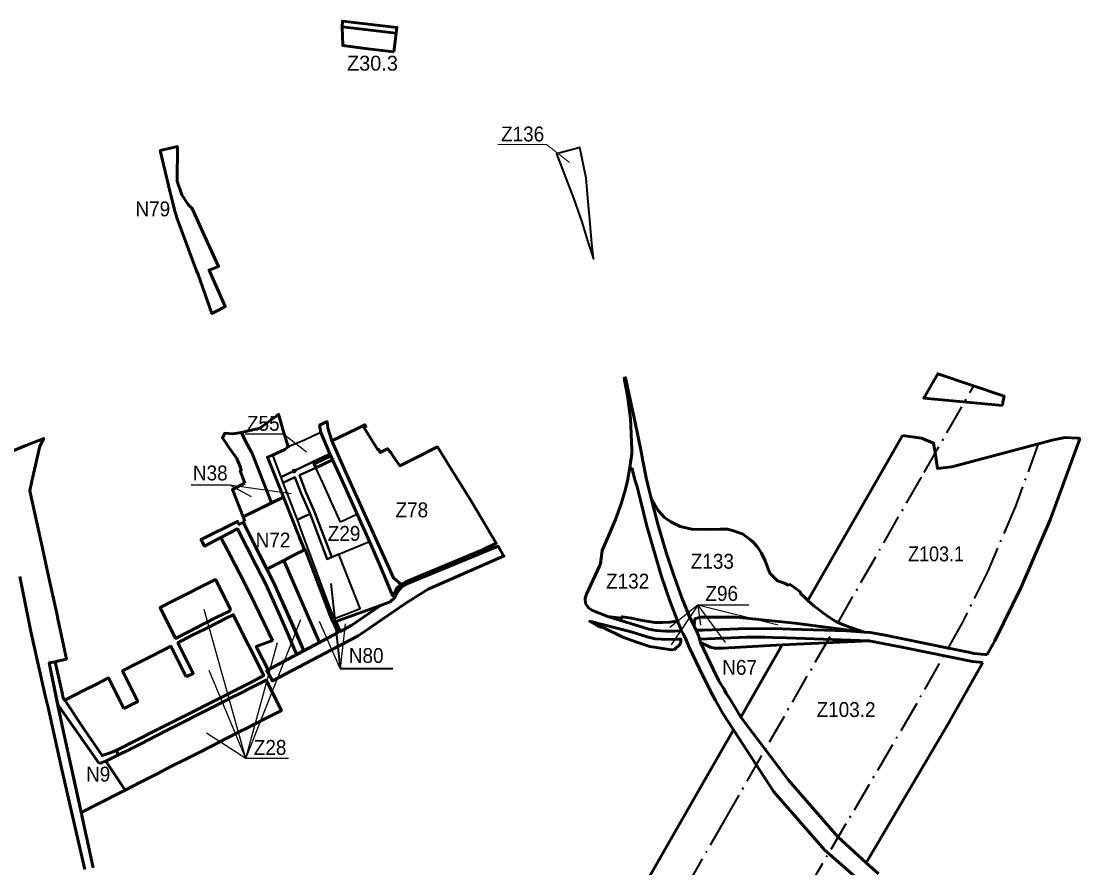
# Model space of a CAD drawing. Extents: x -650277 to -643425, y -1073980 to -1066720.
# Drawn here: x -648765 to -647061, y -1068122 to -1066758 of the extents above; entities that cross this region are included whole.
import ezdxf

# ---------------------------------------------------------------- set-up
doc = ezdxf.new("R2010")
doc.units = 0
doc.header["$LTSCALE"] = 9.6
doc.header["$PDMODE"] = 32
doc.header["$PDSIZE"] = 4.8
doc.linetypes.add('DOT_DASHED', pattern=[7.7, 5, -1.2, 0.3, -1.2])
for name, color, linetype, lineweight in [('1', 7, 'Continuous', 60), ('15', 7, 'Continuous', 60), ('2', 7, 'Continuous', 40), ('3', 7, 'Continuous', 60), ('42', 7, 'Continuous', 60), ('45', 7, 'Continuous', 60), ('48', 7, 'Continuous', 60), ('59', 7, 'Continuous', 25), ('60', 7, 'Continuous', 60), ('61', 7, 'Continuous', 60), ('62', 7, 'DOT_DASHED', 40), ('63', 7, 'Continuous', 25), ('7', 7, 'Continuous', 60), ('9', 7, 'Continuous', 60)]:
    doc.layers.add(name, color=color, linetype=linetype, lineweight=lineweight)

msp = doc.modelspace()

# ---------------------------------------------------------------- linework, layer by layer
at = {"layer": '1'}
msp.add_line((-648609.91, -1067940.58), (-648611.61, -1067932.63), dxfattribs=at)
for points in [[(-647708.71, -1067723.99), (-647721.05, -1067691.73), (-647734.63, -1067652.57), (-647744.61, -1067617.96), (-647758.25, -1067571.79), (-647768.5, -1067529.75), (-647773.96, -1067508.48), (-647777.55, -1067496.95), (-647781.85, -1067479.19), (-647785.64, -1067477.02), (-647789.39, -1067498.84), (-647792.54, -1067511.85), (-647799.39, -1067535.48)], [(-647704.458, -1067572.034), (-647719.661, -1067564.884), (-647729.802, -1067557.462), (-647740.124, -1067546.265), (-647751.41, -1067526.58), (-647740.49, -1067568.67), (-647727.37, -1067614.33), (-647715.92, -1067648.12), (-647702.04, -1067686.86), (-647690.09, -1067716.05), (-647681.91, -1067732.74), (-647680.804, -1067720.745), (-647672, -1067718), (-647643, -1067718), (-647614, -1067718), (-647557, -1067724), (-647520.145, -1067727.879), (-647408.2, -1067742.37)], [(-647799.39, -1067535.48), (-647808.71, -1067561.03), (-647817.59, -1067582.4)], [(-647591.227, -1067593.613), (-647604.415, -1067584.047), (-647606.559, -1067583.309), (-647620.586, -1067578.478), (-647628.441, -1067576.759), (-647640.087, -1067576.306), (-647654.743, -1067576.996), (-647685.968, -1067576.68), (-647704.458, -1067572.034)], [(-647817.59, -1067582.4), (-647829.97, -1067610.62), (-647832.8, -1067631.53), (-647835.06, -1067637.01), (-647855.24, -1067681.26), (-647857.51, -1067687.74), (-647856.9, -1067695.97)], [(-647573.605, -1067614.951), (-647580.539, -1067604.432), (-647586.864, -1067597.411), (-647591.227, -1067593.613)], [(-647530.82, -1067666.65), (-647536.83, -1067663.64), (-647547.663, -1067659.519), (-647560.187, -1067647.458), (-647567.744, -1067627.24), (-647573.605, -1067614.951)], [(-647499.095, -1067691.163), (-647503.97, -1067686.73), (-647510.6, -1067680.86), (-647511.24, -1067677.53), (-647517.74, -1067672.85), (-647520.13, -1067671.13), (-647527.76, -1067665.65), (-647530.82, -1067666.65)], [(-647856.9, -1067695.97), (-647852.3, -1067703.36), (-647845.74, -1067707.59), (-647821.02, -1067717.33)], [(-647474.13, -1067711.81), (-647489.3, -1067700.07), (-647499.095, -1067691.163)], [(-648399.64, -1067763.26), (-648424.14, -1067714.34), (-648435.34, -1067720.01), (-648446.58, -1067725.71), (-648468.97, -1067736.91), (-648480.06, -1067742.47), (-648491.14, -1067748.02), (-648513.23, -1067759.38), (-648488.49, -1067808.76), (-648499.7, -1067814.37)], [(-647453.87, -1067724.97), (-647462.45, -1067719.84), (-647474.13, -1067711.81)], [(-647821.02, -1067717.33), (-647798.5, -1067719.67), (-647798.17, -1067717.58), (-647783.13, -1067719.68), (-647768.53, -1067722.82), (-647745.41, -1067726.6), (-647732.71, -1067727.02), (-647720.45, -1067726.49), (-647708.71, -1067723.99)], [(-647408.2, -1067742.37), (-647440.81, -1067731.38), (-647453.87, -1067724.97)], [(-648611.61, -1067932.63), (-648547.09, -1067899.87), (-648530.81, -1067891.61), (-648508.22, -1067880.38), (-648486.09, -1067868.98), (-648463.91, -1067857.74), (-648441.47, -1067846.37), (-648419.44, -1067835.3), (-648397.04, -1067823.85), (-648374.84, -1067812.43), (-648399.64, -1067763.26)], [(-648499.7, -1067814.37), (-648524.44, -1067765.11), (-648535.61, -1067770.85), (-648557.84, -1067782.26), (-648580.14, -1067793.61), (-648602.3, -1067804.83), (-648577.78, -1067854.07), (-648600.14, -1067865.29)], [(-648600.14, -1067865.29), (-648624.76, -1067816.11), (-648645.11, -1067826.48), (-648668.085, -1067838.186), (-648675.26, -1067841.84), (-648695.27, -1067852.04), (-648664.41, -1067897.91)], [(-648572.5, -1067983.59), (-648546.76, -1067970.44), (-648524.72, -1067958.93), (-648502.59, -1067948), (-648480.12, -1067936.55), (-648457.87, -1067925.4), (-648435.55, -1067913.84), (-648413.41, -1067902.53), (-648402.29, -1067897.02), (-648391.08, -1067891.24), (-648368.78, -1067879.75), (-648346.57, -1067868.56), (-648371.27, -1067819.47), (-648393.35, -1067830.81), (-648415.69, -1067841.98), (-648426.65, -1067847.64), (-648437.89, -1067853.4), (-648460.33, -1067864.88), (-648482.5, -1067876.22), (-648504.92, -1067887.52), (-648527.33, -1067898.74), (-648549.44, -1067910.07), (-648571.88, -1067921.71), (-648591.04, -1067931.62), (-648609.91, -1067940.58)], [(-648664.41, -1067897.91), (-648635.249, -1067941.252), (-648620.658, -1067935.93), (-648611.61, -1067932.63)], [(-648609.91, -1067940.58), (-648629.22, -1067950.214), (-648597.93, -1067996.72), (-648572.5, -1067983.59)]]:
    msp.add_lwpolyline(points, dxfattribs=at)
for points in [[(-648397.98, -1067678.79), (-648373.99, -1067728.95), (-648361.08, -1067755.88), (-648387.04, -1067765.67), (-648384.25, -1067771.07), (-648367.811, -1067802.994), (-648321.623, -1067778.399), (-648326, -1067769), (-648337.32, -1067742.59), (-648348.55, -1067716.71), (-648359.6, -1067691.58), (-648371.34, -1067665.08), (-648386.91, -1067634.83), (-648402.02, -1067605.49), (-648417.12, -1067576.17), (-648443.83, -1067589.92), (-648428.7, -1067619.24), (-648413.57, -1067648.57)], [(-648342.697, -1067626.806), (-648369.949, -1067640.851), (-648359.213, -1067661.956), (-648310.511, -1067772.476), (-648285.254, -1067759.008), (-648296.891, -1067732.172), (-648342.023, -1067628.096)], [(-648519.63, -1067691.58), (-648541.86, -1067702.86), (-648516.73, -1067752.57), (-648494.84, -1067741.06), (-648472.5, -1067729.76), (-648450.23, -1067718.32), (-648430.17, -1067708.33), (-648428.67, -1067705.52), (-648452.72, -1067657.62)]]:
    msp.add_lwpolyline(points, close=True, dxfattribs=at)
at = {"layer": '1', "lineweight": 25}
msp.add_lwpolyline([(-648335, -1067946), (-648404, -1067946), (-648353, -1067759)], dxfattribs=at)
at = {"layer": '15'}
msp.add_line((-648264.34, -1067464.83), (-648267.21, -1067458.61), dxfattribs=at)
for points in [[(-648161.58, -1066777.41), (-648160.51, -1066768.4), (-648248.43, -1066758.34), (-648248.77, -1066767.43)], [(-648362.585, -1067534.204), (-648343.41, -1067524.81), (-648369.01, -1067460.52), (-648361, -1067457.36), (-648341.15, -1067448.14), (-648335.38, -1067444.07), (-648344.41, -1067416.04), (-648349.67, -1067396.88), (-648351.06, -1067391.62), (-648352.16, -1067392.42), (-648353.35, -1067393.29), (-648381.48, -1067413.68), (-648410.92, -1067420.63), (-648409.61, -1067423.44), (-648404.29, -1067434.9), (-648394.92, -1067452.23), (-648393.17, -1067455.88)], [(-648237.81, -1067522.42), (-648204.88, -1067596.54), (-648198.39, -1067610.97), (-648193.8, -1067621), (-648189.03, -1067631.71), (-648167.48, -1067683.45), (-648164.79, -1067678.96), (-648163.11, -1067676.17), (-648160.68, -1067671.55), (-648153.98, -1067665.43), (-648166.173, -1067654.853), (-648240.51, -1067489.9), (-648265.197, -1067434.03), (-648265.197, -1067434.03), (-648272.022, -1067413.59), (-648273.008, -1067403.338), (-648279.24, -1067406.38), (-648285.08, -1067409.24), (-648283.21, -1067420.88), (-648268.67, -1067455.43), (-648267.21, -1067458.61), (-648264.34, -1067464.83), (-648253.1, -1067489.23)], [(-648359.6, -1067691.58), (-648348.55, -1067716.71), (-648337.32, -1067742.59), (-648326, -1067769), (-648321.623, -1067778.399), (-648310.511, -1067772.476), (-648323.178, -1067741.953), (-648359.213, -1067661.956), (-648405.054, -1067571.837), (-648408.002, -1067565.219), (-648414.73, -1067568.8), (-648417.19, -1067564.02), (-648475.78, -1067593.11), (-648473.34, -1067598.06), (-648470.57, -1067603.69), (-648470.47, -1067603.64), (-648443.83, -1067589.92), (-648417.12, -1067576.17), (-648402.02, -1067605.49), (-648386.91, -1067634.83), (-648371.34, -1067665.08)], [(-647988.235, -1067619.912), (-647995.04, -1067608.56), (-647997.68, -1067604.11), (-648144.83, -1067664.48), (-648151.6, -1067668.12), (-648157.2, -1067674.32), (-648161, -1067680.96), (-648162.69, -1067684), (-648164.09, -1067686.51), (-648171.21, -1067693.37), (-648187.139, -1067699.179), (-648233.264, -1067731.288), (-648251.711, -1067741.124), (-648258.96, -1067725.37), (-648262.632, -1067726.711), (-648255.016, -1067742.886), (-648319.983, -1067777.526), (-648370.113, -1067804.22), (-648360.993, -1067821.027), (-648222.872, -1067748.412), (-648146.127, -1067695.8), (-648110.36, -1067673.133), (-647988.052, -1067619.624)]]:
    msp.add_lwpolyline(points, close=True, dxfattribs=at)
for points in [[(-648793.71, -1067456.88), (-648757.97, -1067441.51), (-648728.95, -1067430.33), (-648735.59, -1067442.88), (-648748.53, -1067499.3), (-648751.29, -1067514.57), (-648731.06, -1067607.06), (-648725.8, -1067632.36), (-648720.1, -1067657.12), (-648708.26, -1067712.07), (-648706.08, -1067723.56), (-648702.33, -1067740.84), (-648692.53, -1067785.79), (-648704.614, -1067788.491), (-648710.961, -1067789.906), (-648720.34, -1067792), (-648696.93, -1067905.76), (-648672.31, -1068017.25), (-648668.92, -1068032.96), (-648651.89, -1068111.95), (-648649.74, -1068121.95)], [(-648267.21, -1067458.61), (-648294.04, -1067471.35), (-648291.172, -1067477.571), (-648264.34, -1067464.83)], [(-648662.71, -1068124.76), (-648677.61, -1068061.74), (-648700.16, -1067963.42), (-648722.09, -1067863.84), (-648727.05, -1067844.33), (-648738.7, -1067792.04), (-648749.97, -1067741.49), (-648767.84, -1067652.98)], [(-648710.961, -1067789.906), (-648720.34, -1067792), (-648706.687, -1067858.345), (-648640, -1067954)], [(-648695.27, -1067852.04), (-648697.7, -1067848.43), (-648699.621, -1067840.06), (-648699.593, -1067840.046), (-648710.96, -1067789.91)], [(-648611.61, -1067932.63), (-648620.658, -1067935.93), (-648635.249, -1067941.252), (-648664.41, -1067897.91), (-648695.27, -1067852.04)], [(-648640, -1067954), (-648629.22, -1067950.214), (-648609.91, -1067940.58), (-648611.61, -1067932.63)]]:
    msp.add_lwpolyline(points, dxfattribs=at)
at = {"layer": '2'}
msp.add_line((-648347.51, -1067492.87), (-648326.09, -1067482.7), dxfattribs=at)
for points in [[(-647876.57, -1067043.5), (-647863.04, -1067081.36), (-647853.65, -1067111.91), (-647844.3, -1067141.25), (-647847.09, -1067110.58), (-647850.07, -1067077.71), (-647852.63, -1067049.52), (-647856.11, -1067011.21), (-647866.14, -1066961.98), (-647871.52, -1066963.43), (-647903.5, -1066972.05), (-647903.5, -1066972.05)], [(-648324.735, -1067492.8), (-648344.186, -1067501.627), (-648334.09, -1067528.2), (-648321.36, -1067561.69), (-648300.258, -1067551.772), (-648314.647, -1067519.171)], [(-648251.33, -1067565.28), (-648279.86, -1067502.11), (-648291.17, -1067477.57), (-648317.435, -1067489.488), (-648307.57, -1067515.44), (-648292.991, -1067548.356), (-648265.601, -1067621.762), (-648254.04, -1067616.96), (-648204.88, -1067596.54), (-648224.16, -1067552.55)]]:
    msp.add_lwpolyline(points, close=True, dxfattribs=at)
for points in [[(-648268.67, -1067455.43), (-648283.21, -1067420.88), (-648295.66, -1067426.76), (-648309.57, -1067433.34), (-648335.38, -1067444.07), (-648341.15, -1067448.14)], [(-648341.15, -1067448.14), (-648361, -1067457.36), (-648347.51, -1067492.87)], [(-648268.67, -1067455.43), (-648297.915, -1067469.319), (-648326.09, -1067482.7), (-648347.51, -1067492.87), (-648344.186, -1067501.627), (-648324.735, -1067492.8), (-648314.647, -1067519.171), (-648300.258, -1067551.772), (-648300.258, -1067551.772), (-648272.941, -1067624.811), (-648265.601, -1067621.762), (-648292.991, -1067548.356), (-648307.57, -1067515.44), (-648317.435, -1067489.488), (-648291.172, -1067477.571), (-648294.04, -1067471.35)], [(-648326.09, -1067482.7), (-648295.409, -1067468.129), (-648268.67, -1067455.43)], [(-648294.04, -1067471.35), (-648267.21, -1067458.61), (-648268.67, -1067455.43)], [(-648314.647, -1067519.171), (-648324.735, -1067492.8), (-648344.186, -1067501.627)], [(-648344.186, -1067501.627), (-648334.09, -1067528.2), (-648321.36, -1067561.69)], [(-648321.36, -1067561.69), (-648300.258, -1067551.772), (-648314.647, -1067519.171)], [(-648254.04, -1067616.96), (-648265.601, -1067621.762), (-648272.941, -1067624.811), (-648300.258, -1067551.772), (-648300.258, -1067551.772), (-648321.36, -1067561.69)], [(-648321.36, -1067561.69), (-648311.95, -1067586.45), (-648265.08, -1067712.06)], [(-648265.08, -1067712.06), (-648261.25, -1067720.39), (-648235.78, -1067710.79), (-648219.86, -1067704.42), (-648247.53, -1067633.53), (-648254.04, -1067616.96)]]:
    msp.add_lwpolyline(points, dxfattribs=at)
msp.add_point((-648326.09, -1067482.7), dxfattribs=at)
at = {"layer": '3'}
msp.add_lwpolyline([(-648165.33, -1066807.74), (-648162.8, -1066786.8), (-648161.58, -1066777.41), (-648248.77, -1066767.43), (-648247.78, -1066797.53), (-648211.58, -1066802.18)], close=True, dxfattribs=at)
at = {"layer": '42'}
msp.add_lwpolyline([(-647606.818, -1067879.061), (-647540.208, -1067762.876), (-647635.758, -1067768.38), (-647649.22, -1067768.38), (-647656.469, -1067766.309), (-647672.05, -1067758.98), (-647650.8, -1067803.28), (-647642.29, -1067820.76), (-647637.21, -1067829.29), (-647633.69, -1067834.31), (-647630.3, -1067841.02), (-647625.37, -1067848.86), (-647617.25, -1067861.95)], close=True, dxfattribs=at)
at = {"layer": '45'}
msp.add_lwpolyline([(-648405.41, -1067563.84), (-648408.002, -1067565.219), (-648369.949, -1067640.851), (-648342.697, -1067626.806), (-648328.54, -1067619.51), (-648309.522, -1067609.713), (-648317.43, -1067590), (-648343.41, -1067524.81), (-648408.26, -1067556.58)], close=True, dxfattribs=at)
at = {"layer": '48'}
for points in [[(-648528.01, -1067023.13), (-648518.72, -1067061.99), (-648514.86, -1067074.83), (-648507.88, -1067093.9), (-648483.31, -1067160.63), (-648480.57, -1067166.13), (-648458.73, -1067229.1), (-648449.03, -1067224.14), (-648437.02, -1067217.99), (-648462.97, -1067159.24), (-648447.66, -1067153.25), (-648467.56, -1067110.02), (-648490.23, -1067060.06), (-648496.87, -1067053.5), (-648506.78, -1067037.81), (-648514.38, -1067016.2), (-648513.842, -1066960.243), (-648541.52, -1066966.657)], [(-648405.27, -1067502.27), (-648425.5, -1067512.73), (-648408.26, -1067556.58), (-648362.585, -1067534.205), (-648393.17, -1067455.88), (-648394.92, -1067452.23), (-648404.29, -1067434.9), (-648410.92, -1067420.63), (-648425, -1067423.05), (-648437.75, -1067421.99), (-648441.48, -1067429.63), (-648430.4, -1067445.51), (-648418.3, -1067462.86), (-648412.46, -1067477.42), (-648411.25, -1067481.73), (-648412.89, -1067482.55)], [(-648342.023, -1067628.096), (-648296.891, -1067732.172), (-648285.254, -1067759.008), (-648255.016, -1067742.886), (-648265.614, -1067720.378), (-648269.27, -1067712.6), (-648308.43, -1067609.15), (-648328.54, -1067619.51), (-648342.697, -1067626.806)], [(-648258.96, -1067725.37), (-648251.711, -1067741.124), (-648233.264, -1067731.288), (-648187.139, -1067699.179)]]:
    msp.add_lwpolyline(points, close=True, dxfattribs=at)
at = {"layer": '59', "lineweight": 35}
for p, q in [((-648267, -1067664), (-648252, -1067801)), ((-648252, -1067801), (-648167, -1067801))]:
    msp.add_line(p, q, dxfattribs=at)
at = {"layer": '59', "lineweight": 13}
msp.add_lwpolyline([(-647998, -1066957), (-647920, -1066957), (-647883, -1066986)], dxfattribs=at)
at = {"layer": '59'}
for points in [[(-648405, -1067423), (-648343, -1067423), (-648306, -1067452)], [(-648492, -1067505), (-648430, -1067505), (-648331, -1067519)]]:
    msp.add_lwpolyline(points, dxfattribs=at)
at = {"layer": '60'}
for points in [[(-647606.818, -1067879.061), (-647617.25, -1067861.95), (-647625.37, -1067848.86), (-647630.3, -1067841.02), (-647633.69, -1067834.31), (-647637.21, -1067829.29), (-647642.29, -1067820.76), (-647650.8, -1067803.28), (-647672.05, -1067758.98), (-647673.47, -1067753.48), (-647673.47, -1067753.48), (-647674.67, -1067748.73), (-647676.47, -1067744.5), (-647678.66, -1067739.38), (-647681.91, -1067732.74), (-647690.09, -1067716.05), (-647702.04, -1067686.86), (-647715.92, -1067648.12), (-647727.37, -1067614.33), (-647740.49, -1067568.67), (-647751.41, -1067526.58), (-647756.55, -1067505.32), (-647759.16, -1067494.01), (-647764.89, -1067466.64), (-647768.5, -1067446.04), (-647778.78, -1067397.1), (-647792.52, -1067332.74), (-647794.54, -1067333.14), (-647788.77, -1067365.03), (-647784.55, -1067398.01), (-647782.39, -1067448.34), (-647782.5, -1067455.11), (-647784.36, -1067469.6), (-647785.64, -1067477.02), (-647781.85, -1067479.19), (-647777.55, -1067496.95), (-647773.96, -1067508.48), (-647768.5, -1067529.75), (-647758.25, -1067571.79), (-647744.61, -1067617.96), (-647734.63, -1067652.57), (-647721.05, -1067691.73), (-647708.71, -1067723.99), (-647702.21, -1067740.43), (-647699.89, -1067745.24), (-647697.85, -1067749.46), (-647695.71, -1067753.9), (-647690.19, -1067766.37), (-647668.13, -1067812.76), (-647651.94, -1067844.36), (-647648.33, -1067851.17), (-647643.83, -1067859.13), (-647635.77, -1067873.43), (-647618.773, -1067899.914)], [(-647783.54, -1067742.11), (-647850.45, -1067724.77), (-647838.18, -1067731.62), (-647832.56, -1067734.22), (-647829.49, -1067734.58), (-647796.87, -1067750.25), (-647774.54, -1067758.68), (-647753.53, -1067765.58), (-647718.54, -1067770.6), (-647712.01, -1067769.63), (-647712.26, -1067767.28)], [(-647712.26, -1067767.28), (-647711.773, -1067767.135), (-647711.286, -1067766.968), (-647710.799, -1067766.777), (-647710.315, -1067766.562), (-647709.834, -1067766.324), (-647709.359, -1067766.062), (-647708.892, -1067765.776), (-647708.433, -1067765.466), (-647707.985, -1067765.133), (-647707.55, -1067764.777), (-647707.128, -1067764.398), (-647706.723, -1067763.999), (-647706.335, -1067763.579), (-647705.966, -1067763.14), (-647705.617, -1067762.683), (-647705.29, -1067762.21), (-647704.985, -1067761.721), (-647704.704, -1067761.22), (-647704.447, -1067760.707), (-647704.216, -1067760.184), (-647704.01, -1067759.653), (-647703.83, -1067759.117), (-647703.675, -1067758.576), (-647703.547, -1067758.033), (-647703.445, -1067757.489), (-647703.368, -1067756.946), (-647703.315, -1067756.406), (-647703.287, -1067755.87), (-647703.282, -1067755.341), (-647703.3, -1067754.818), (-647703.34, -1067754.304), (-647703.4, -1067753.8), (-647711.09, -1067753.71), (-647728.98, -1067754.07), (-647734.69, -1067753.66), (-647744.74, -1067752.93), (-647757.74, -1067749.96), (-647759.13, -1067749.54), (-647783.54, -1067742.11)], [(-647405.026, -1068113.904), (-647451.024, -1068071.886), (-647530.038, -1067980.839), (-647606.818, -1067879.061)], [(-647618.773, -1067899.914), (-647553.628, -1067999.427), (-647472.338, -1068093.096), (-647419.713, -1068138.871)], [(-647385.13, -1068131.51), (-647405.026, -1068113.904)]]:
    msp.add_lwpolyline(points, dxfattribs=at)
for points in [[(-647754.88, -1067737.59), (-647743.12, -1067739.93), (-647728.29, -1067740.64), (-647713.15, -1067741), (-647702.21, -1067740.43), (-647708.71, -1067723.99), (-647720.45, -1067726.49), (-647732.71, -1067727.02), (-647745.41, -1067726.6), (-647768.53, -1067722.82), (-647783.13, -1067719.68), (-647798.17, -1067717.58), (-647798.5, -1067719.67), (-647821.02, -1067717.33)], [(-647596.91, -1067736.61), (-647572.33, -1067737.03), (-647555.58, -1067736.71), (-647525.685, -1067737.542), (-647436.72, -1067740.02), (-647408.2, -1067742.37), (-647520.145, -1067727.879), (-647557, -1067724), (-647614, -1067718), (-647643, -1067718), (-647672, -1067718), (-647680.804, -1067720.745), (-647681.91, -1067732.74), (-647678.66, -1067739.38), (-647678.66, -1067739.38), (-647667.76, -1067739.01), (-647638.75, -1067738.03)], [(-647540.208, -1067762.876), (-647400.63, -1067756.19), (-647533.597, -1067751.344), (-647555.67, -1067750.91), (-647568.36, -1067750.7), (-647597.83, -1067750.21), (-647673.47, -1067753.48), (-647672.05, -1067758.98), (-647672.05, -1067758.98), (-647656.469, -1067766.309), (-647649.22, -1067768.38), (-647635.758, -1067768.38)]]:
    msp.add_lwpolyline(points, close=True, dxfattribs=at)
at = {"layer": '61'}
msp.add_lwpolyline([(-647185.93, -1067377.38), (-647184.97, -1067372.22), (-647183.09, -1067362.16), (-647289.924, -1067326.309), (-647312.383, -1067365.484)], close=True, dxfattribs=at)
for points in [[(-647346.944, -1067425.768), (-647364.024, -1067455.561), (-647499.095, -1067691.163), (-647489.3, -1067700.07)], [(-647243.39, -1067469.81), (-647252.99, -1067472.35), (-647267.49, -1067476.23), (-647290.23, -1067478.89), (-647292.51, -1067464.56), (-647294.31, -1067453.26), (-647296.75, -1067437.91), (-647315.89, -1067429.71), (-647346.944, -1067425.768)], [(-647061.252, -1067430.908), (-647061.252, -1067430.908), (-647063.45, -1067430.19), (-647064.87, -1067429.73), (-647084.77, -1067428.64), (-647103.55, -1067432.54), (-647243.39, -1067469.81)], [(-647210.537, -1067778.594), (-647198.088, -1067756.5), (-647155.592, -1067670.17), (-647108.971, -1067561.55), (-647061.252, -1067430.908)], [(-647489.3, -1067700.07), (-647474.13, -1067711.81), (-647462.45, -1067719.84), (-647453.87, -1067724.97), (-647440.81, -1067731.38), (-647408.2, -1067742.37), (-647398.74, -1067743.15), (-647374.55, -1067747.34)], [(-647374.55, -1067747.34), (-647280.78, -1067766.44), (-647237.91, -1067775.18), (-647231.17, -1067776.55), (-647213.92, -1067778.26), (-647210.537, -1067778.594)], [(-647400.63, -1067756.19), (-647540.208, -1067762.876), (-647593.267, -1067855.425), (-647606.818, -1067879.061)], [(-647217.611, -1067791.149), (-647233.83, -1067789.69), (-647345.11, -1067767.28), (-647400.63, -1067756.19)], [(-647405.026, -1068113.904), (-647273.297, -1067889.981), (-647217.611, -1067791.149)], [(-647606.818, -1067879.061), (-647530.038, -1067980.839), (-647451.024, -1068071.886), (-647405.026, -1068113.904)], [(-647464.94, -1068215.752), (-647461.188, -1068209.373), (-647419.713, -1068138.871), (-647472.338, -1068093.096), (-647553.628, -1067999.427), (-647618.773, -1067899.914), (-647685.819, -1068016.861)], [(-647685.819, -1068016.861), (-647781.346, -1068183.485), (-647791.055, -1068200.507)]]:
    msp.add_lwpolyline(points, dxfattribs=at)
at = {"layer": '62'}
for points in [[(-647729.261, -1068213.27), (-647633.767, -1068046.703), (-647560.654, -1067919.174), (-647311.972, -1067485.403), (-647231.921, -1067345.773)], [(-647128.118, -1067439.088), (-647164.761, -1067539.408), (-647210.113, -1067645.071), (-647251.182, -1067728.502), (-647325.296, -1067860.04), (-647512.903, -1068178.95), (-647726.877, -1068542.68), (-647850.594, -1068756.441), (-647875.691, -1068807.609), (-647903.473, -1068876.174), (-647924.037, -1068940.973), (-647945.559, -1069039.601), (-647956.348, -1069145.994), (-647956.677, -1069214.977), (-647954.925, -1069248.93), (-647950.785, -1069292.731), (-647945.699, -1069329.377), (-647937.748, -1069374.683)]]:
    msp.add_lwpolyline(points, dxfattribs=at)
at = {"layer": '63'}
for p, q in [((-648430, -1067505), (-648395, -1067524)), ((-648404, -1067946), (-648471, -1067706)), ((-647676, -1067699), (-647672, -1067731)), ((-647676, -1067699), (-647632, -1067759)), ((-648404, -1067946), (-648315, -1067722)), ((-648252, -1067801), (-648285, -1067725)), ((-648244, -1067729), (-648252, -1067801)), ((-648404, -1067946), (-648463, -1067804))]:
    msp.add_line(p, q, dxfattribs=at)
for points in [[(-647594, -1067699), (-647676, -1067699), (-647721, -1067735)], [(-647547, -1067731), (-647676, -1067699), (-647719, -1067763)], [(-648335, -1067946), (-648404, -1067946), (-648467, -1067905)]]:
    msp.add_lwpolyline(points, dxfattribs=at)
at = {"layer": '7'}
msp.add_lwpolyline([(-648640, -1067954), (-648706.687, -1067858.345), (-648696.93, -1067905.76), (-648668.92, -1068032.96), (-648605.323, -1068000.463), (-648597.93, -1067996.72), (-648629.22, -1067950.214)], close=True, dxfattribs=at)
at = {"layer": '9'}
msp.add_lwpolyline([(-648153.98, -1067665.43), (-648149.933, -1067663.646), (-648146.21, -1067661.3), (-648023.96, -1067610.13), (-648000.63, -1067599.14), (-648031.77, -1067546.6), (-648045.04, -1067525.15), (-648076.32, -1067474.6), (-648081.31, -1067466.54), (-648095.28, -1067444.06), (-648133.56, -1067463.2), (-648150.46, -1067471.66), (-648155.85, -1067474.35), (-648164.24, -1067462.15), (-648166.97, -1067458.18), (-648170.38, -1067453.23), (-648175.94, -1067446.89), (-648187.44, -1067452.8), (-648190.23, -1067447.83), (-648191.46, -1067448.59), (-648213.34, -1067413.46), (-648210.48, -1067411.68), (-648211.08, -1067410.6), (-648212.32, -1067408.39), (-648224.19, -1067414.14), (-648265.197, -1067434.03), (-648240.51, -1067489.9), (-648240.51, -1067489.9), (-648166.173, -1067654.853)], close=True, dxfattribs=at)

# ---------------------------------------------------------------- texts
at = {"layer": '59', "width": 0.95}
for s, p in [('Z136', (-647993, -1066952)), ('Z55', (-648402, -1067418)), ('N38', (-648489, -1067498)), ('Z29', (-648271.915, -1067595.341)), ('N80', (-648238, -1067792))]:
    msp.add_text(s, height=24, dxfattribs=at).set_placement(p)
at = {"layer": '63'}
msp.add_text('Z30.3', height=24, dxfattribs=at).set_placement((-648241, -1066838))
for s, width, p in [('N79', 0.95, (-648581.544, -1067072.648)), ('Z78', 0.95, (-648162.836, -1067557.421)), ('N72', 0.95, (-648388, -1067606)), ('Z103.1', 0.9, (-647337.666, -1067628.26)), ('Z133', 0.95, (-647687.579, -1067640.215)), ('Z132', 0.95, (-647823.879, -1067672.215)), ('Z96', 0.95, (-647664, -1067692)), ('N67', 0.95, (-647636.885, -1067811.038)), ('Z103.2', 0.95, (-647485, -1067879)), ('Z28', 0.95, (-648391, -1067940)), ('N9', 0.95, (-648661, -1067983))]:
    msp.add_text(s, height=24, dxfattribs=dict(at, width=width)).set_placement(p)

doc.saveas('drawing.dxf')
